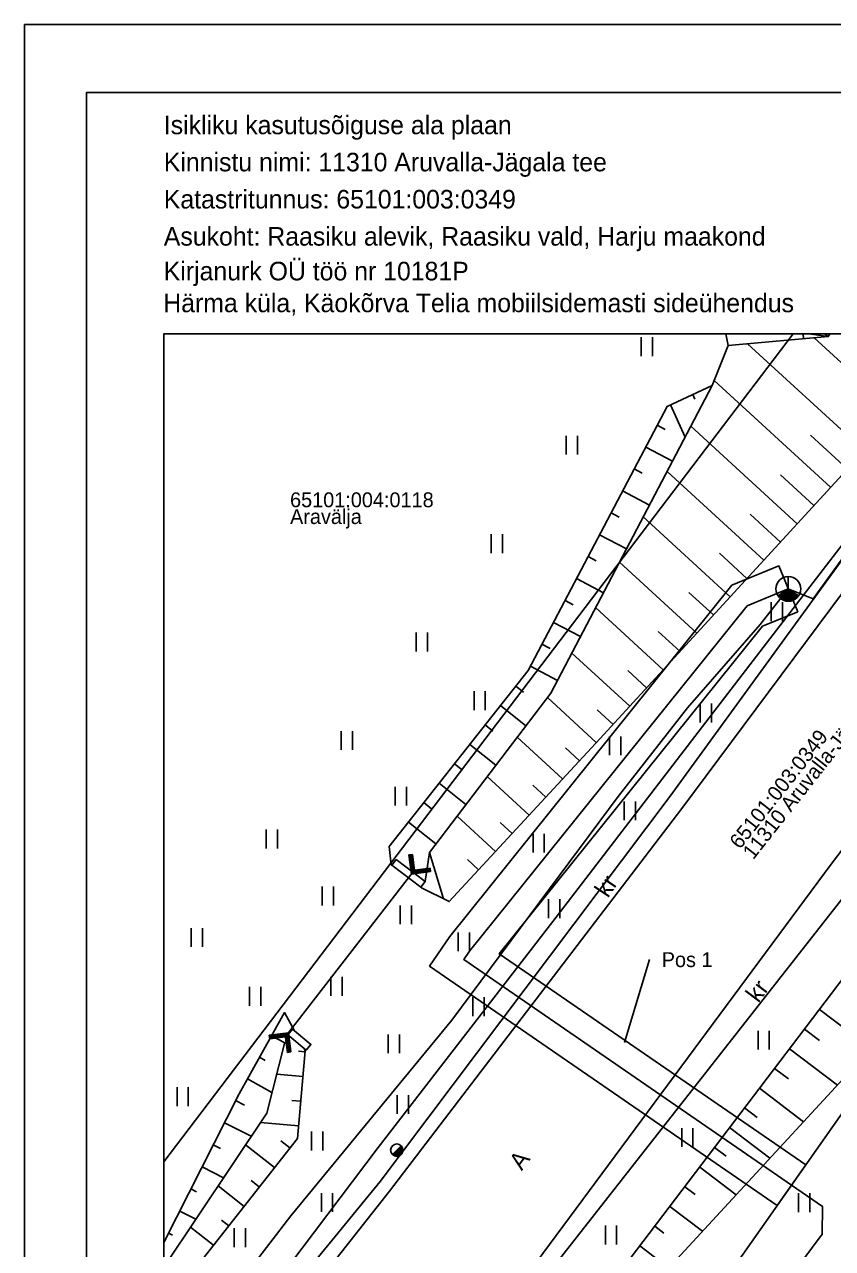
# Model space of a CAD drawing. Extents: x 565784.5 to 565837, y 6571808.3 to 6571882.6.
# Drawn here: x 565784.51 to 565817.14, y 6571833.15 to 6571882.59 of the extents above; entities that cross this region are included whole.
import ezdxf

# ---------------------------------------------------------------- set-up
doc = ezdxf.new("R2010")
doc.units = 0
for name, color, linetype in [('HALJASTUS', 7, 'Continuous'), ('KASUTUSALA', 7, 'Continuous'), ('PIIR', 7, 'Continuous'), ('POST', 7, 'Continuous'), ('PR_SIDE', 7, 'Continuous'), ('RELJEEF', 7, 'Continuous'), ('SIKAEV', 7, 'Continuous'), ('SITRASS', 7, 'Continuous'), ('TEE', 7, 'Continuous'), ('TRUUP', 7, 'Continuous'), ('VORMISTUS', 7, 'Continuous')]:
    doc.layers.add(name, color=color, linetype=linetype)

msp = doc.modelspace()

# ---------------------------------------------------------------- linework, layer by layer
at = {"layer": 'HALJASTUS'}
for p, q in [((565809.42, 6571869.956), (565809.42, 6571869.195)), ((565809.875, 6571869.956), (565809.875, 6571869.195)), ((565806.389, 6571865.979), (565806.389, 6571865.218)), ((565806.844, 6571865.979), (565806.844, 6571865.218)), ((565803.358, 6571862.003), (565803.358, 6571861.242)), ((565803.813, 6571862.003), (565803.813, 6571861.242)), ((565814.662, 6571859.257), (565814.662, 6571858.496)), ((565815.117, 6571859.257), (565815.117, 6571858.496)), ((565800.327, 6571858.026), (565800.327, 6571857.265)), ((565800.783, 6571858.026), (565800.783, 6571857.265)), ((565802.664, 6571855.656), (565802.664, 6571854.895)), ((565803.119, 6571855.656), (565803.119, 6571854.895)), ((565811.794, 6571855.164), (565811.794, 6571854.403)), ((565812.249, 6571855.164), (565812.249, 6571854.403)), ((565797.297, 6571854.049), (565797.297, 6571853.288)), ((565797.752, 6571854.049), (565797.752, 6571853.288)), ((565808.132, 6571853.836), (565808.132, 6571853.075)), ((565808.587, 6571853.836), (565808.587, 6571853.075)), ((565799.48, 6571851.8), (565799.48, 6571851.039)), ((565799.935, 6571851.8), (565799.935, 6571851.039)), ((565808.734, 6571851.209), (565808.734, 6571850.448)), ((565809.189, 6571851.209), (565809.189, 6571850.448)), ((565794.266, 6571850.073), (565794.266, 6571849.312)), ((565794.721, 6571850.073), (565794.721, 6571849.312)), ((565805.047, 6571849.901), (565805.047, 6571849.14)), ((565805.502, 6571849.901), (565805.502, 6571849.14)), ((565796.526, 6571847.768), (565796.526, 6571847.007)), ((565796.981, 6571847.768), (565796.981, 6571847.007)), ((565805.675, 6571847.254), (565805.675, 6571846.493)), ((565806.13, 6571847.254), (565806.13, 6571846.493)), ((565799.682, 6571847.009), (565799.682, 6571846.248)), ((565800.137, 6571847.009), (565800.137, 6571846.248)), ((565791.235, 6571846.096), (565791.235, 6571845.335)), ((565791.69, 6571846.096), (565791.69, 6571845.335)), ((565802.029, 6571845.917), (565802.029, 6571845.156)), ((565802.484, 6571845.917), (565802.484, 6571845.156)), ((565796.879, 6571844.119), (565796.879, 6571843.357)), ((565797.334, 6571844.119), (565797.334, 6571843.357)), ((565793.597, 6571843.716), (565793.597, 6571842.955)), ((565794.052, 6571843.716), (565794.052, 6571842.955)), ((565802.616, 6571843.299), (565802.616, 6571842.538)), ((565803.071, 6571843.299), (565803.071, 6571842.538)), ((565799.2, 6571841.795), (565799.2, 6571841.034)), ((565799.655, 6571841.795), (565799.655, 6571841.034)), ((565814.134, 6571841.947), (565814.134, 6571841.186)), ((565814.589, 6571841.947), (565814.589, 6571841.186)), ((565790.667, 6571839.664), (565790.667, 6571838.903)), ((565791.122, 6571839.664), (565791.122, 6571838.903)), ((565799.557, 6571839.345), (565799.557, 6571838.583)), ((565800.012, 6571839.345), (565800.012, 6571838.583)), ((565796.096, 6571837.876), (565796.096, 6571837.115)), ((565796.551, 6571837.876), (565796.551, 6571837.115)), ((565811.05, 6571838.011), (565811.05, 6571837.25)), ((565811.506, 6571838.011), (565811.506, 6571837.25)), ((565796.498, 6571835.39), (565796.498, 6571834.628)), ((565796.953, 6571835.39), (565796.953, 6571834.628)), ((565815.772, 6571835.381), (565815.772, 6571834.619)), ((565816.228, 6571835.381), (565816.228, 6571834.619)), ((565792.978, 6571833.966), (565792.978, 6571833.205)), ((565793.433, 6571833.966), (565793.433, 6571833.205)), ((565807.967, 6571834.076), (565807.967, 6571833.314)), ((565808.422, 6571834.076), (565808.422, 6571833.314))]:
    msp.add_line(p, q, dxfattribs=at)
at = {"layer": 'KASUTUSALA'}
msp.add_lwpolyline([(565815.738, 6571858.869), (565814.976, 6571860.719), (565813.082, 6571859.939), (565801.68, 6571845.752), (565800.866, 6571844.561), (565814.913, 6571834.887), (565816.063, 6571836.523), (565803.681, 6571845.05), (565814.319, 6571858.285)], close=True, dxfattribs=at)
at = {"layer": 'PIIR'}
for points in [[(565790.132, 6571836.654), (565815.559, 6571870.093)], [(565815.559, 6571870.093), (565790.132, 6571836.654)], [(565831.382, 6571858.328), (565803.59, 6571818.77), (565802.507, 6571817.593)], [(565803.77, 6571817.593), (565803.59, 6571818.77), (565831.382, 6571858.328)]]:
    msp.add_lwpolyline(points, dxfattribs=at)
at = {"layer": 'POST'}
msp.add_line((565799.366, 6571836.946), (565799.719, 6571837.299), dxfattribs=at)
msp.add_circle((565799.543, 6571837.122), 0.25, dxfattribs=at)
for radius, start, end in [(0.225, 224.8541, 45.0356), (0.2, 224.8427, 45.047), (0.175, 224.8281, 45.0616), (0.15, 224.8087, 45.081), (0.125, 224.7814, 45.1083), (0.1, 224.7406, 45.1491), (0.075, 224.6725, 45.2172), (0.05, 224.5363, 45.3534), (0.025, 224.1278, 45.7619)]:
    msp.add_arc((565799.543, 6571837.122), radius, start, end, dxfattribs=at)
at = {"layer": 'PR_SIDE'}
msp.add_lwpolyline([(565805.611, 6571817.593), (565805.669, 6571817.785), (565806.328, 6571819.758), (565816.728, 6571833.724), (565816.733, 6571834.847), (565802.253, 6571844.819), (565802.484, 6571845.156), (565813.7, 6571859.112), (565815.357, 6571859.794)], dxfattribs=at)
at = {"layer": 'RELJEEF'}
for p, q in [((565815.972, 6571869.899), (565815.955, 6571870.093)), ((565819.772, 6571866.846), (565816.402, 6571869.937)), ((565818.419, 6571865.372), (565813.704, 6571869.699)), ((565817.067, 6571863.898), (565812.369, 6571868.209)), ((565811.501, 6571867.642), (565811.584, 6571867.46)), ((565810.593, 6571867.224), (565811.193, 6571865.92)), ((565810.062, 6571866.407), (565810.388, 6571866.236)), ((565815.715, 6571862.425), (565811.424, 6571866.361)), ((565817.743, 6571864.635), (565816.249, 6571866.006)), ((565809.597, 6571865.522), (565810.683, 6571864.95)), ((565809.131, 6571864.637), (565809.457, 6571864.465)), ((565814.363, 6571860.951), (565810.462, 6571864.53)), ((565816.391, 6571863.162), (565815.046, 6571864.396)), ((565808.666, 6571863.752), (565809.753, 6571863.18)), ((565808.2, 6571862.867), (565808.527, 6571862.695)), ((565813.011, 6571859.477), (565809.5, 6571862.699)), ((565815.039, 6571861.688), (565813.81, 6571862.815)), ((565807.735, 6571861.982), (565808.823, 6571861.409)), ((565807.269, 6571861.097), (565807.596, 6571860.925)), ((565813.687, 6571860.214), (565812.575, 6571861.234)), ((565811.659, 6571858.003), (565808.538, 6571860.867)), ((565806.804, 6571860.212), (565807.892, 6571859.639)), ((565812.335, 6571858.74), (565811.34, 6571859.653)), ((565806.338, 6571859.327), (565806.665, 6571859.155)), ((565810.307, 6571856.53), (565807.576, 6571859.036)), ((565805.873, 6571858.442), (565806.962, 6571857.868)), ((565810.983, 6571857.267), (565810.105, 6571858.072)), ((565805.407, 6571857.557), (565805.734, 6571857.385)), ((565808.955, 6571855.056), (565806.613, 6571857.204)), ((565804.942, 6571856.671), (565806.032, 6571856.098)), ((565809.631, 6571855.793), (565808.87, 6571856.491)), ((565804.351, 6571855.868), (565804.656, 6571855.627)), ((565803.731, 6571855.083), (565804.761, 6571854.269)), ((565807.602, 6571853.583), (565805.629, 6571855.41)), ((565808.279, 6571854.319), (565807.635, 6571854.91)), ((565803.111, 6571854.298), (565803.424, 6571854.051)), ((565802.491, 6571853.514), (565803.549, 6571852.678)), ((565806.243, 6571852.115), (565804.412, 6571853.811)), ((565806.923, 6571852.849), (565806.352, 6571853.378)), ((565801.871, 6571852.729), (565802.193, 6571852.475)), ((565804.885, 6571850.648), (565803.194, 6571852.213)), ((565801.251, 6571851.945), (565802.337, 6571851.087)), ((565805.564, 6571851.382), (565805.036, 6571851.871)), ((565800.631, 6571851.16), (565800.961, 6571850.9)), ((565803.526, 6571849.18), (565801.977, 6571850.614)), ((565800.011, 6571850.376), (565801.125, 6571849.495)), ((565804.205, 6571849.914), (565803.719, 6571850.364)), ((565800.688, 6571847.978), (565800.861, 6571849.149)), ((565801.433, 6571847.277), (565800.861, 6571849.149)), ((565802.847, 6571848.446), (565802.403, 6571848.857)), ((565816.618, 6571842.808), (565818.701, 6571841.225)), ((565794.49, 6571841.746), (565795.017, 6571841.451)), ((565816.013, 6571842.012), (565816.615, 6571841.555)), ((565815.408, 6571841.216), (565817.338, 6571839.749)), ((565794.001, 6571840.873), (565794.229, 6571840.746)), ((565795.843, 6571841.093), (565795.574, 6571841.117)), ((565795.754, 6571840.097), (565794.694, 6571840.192)), ((565814.803, 6571840.42), (565815.359, 6571839.997)), ((565793.513, 6571840.001), (565794.503, 6571839.447)), ((565814.198, 6571839.624), (565815.975, 6571838.272)), ((565793.036, 6571839.122), (565793.393, 6571838.941)), ((565795.664, 6571839.101), (565795.298, 6571839.134)), ((565813.592, 6571838.828), (565814.103, 6571838.44)), ((565792.585, 6571838.23), (565793.665, 6571837.683)), ((565795.575, 6571838.105), (565794.04, 6571838.243)), ((565812.987, 6571838.032), (565814.612, 6571836.796)), ((565792.133, 6571837.338), (565792.424, 6571837.19)), ((565794.609, 6571836.425), (565793.438, 6571837.344)), ((565795.226, 6571837.212), (565794.857, 6571837.502)), ((565812.382, 6571837.235), (565812.847, 6571836.882)), ((565791.681, 6571836.446), (565792.545, 6571836.008)), ((565811.777, 6571836.439), (565813.249, 6571835.32)), ((565793.991, 6571835.639), (565793.658, 6571835.9)), ((565791.229, 6571835.554), (565791.455, 6571835.439)), ((565793.374, 6571834.852), (565792.323, 6571835.677)), ((565811.172, 6571835.643), (565811.591, 6571835.325)), ((565810.567, 6571834.847), (565811.887, 6571833.844)), ((565790.777, 6571834.662), (565791.425, 6571834.333)), ((565792.757, 6571834.065), (565792.459, 6571834.298)), ((565790.325, 6571833.77), (565790.487, 6571833.688)), ((565792.139, 6571833.278), (565791.208, 6571834.009)), ((565809.961, 6571834.051), (565810.335, 6571833.767)), ((565809.356, 6571833.255), (565810.524, 6571832.368))]:
    msp.add_line(p, q, dxfattribs=at)
for points in [[(565800.51, 6571847.744), (565800.538, 6571847.723), (565801.66, 6571847.165), (565807.743, 6571853.735), (565820.396, 6571867.526), (565822.365, 6571870.093)], [(565816.969, 6571869.988), (565812.929, 6571869.63), (565812.828, 6571870.093)], [(565800.861, 6571849.149), (565805.762, 6571855.585), (565812.288, 6571868.004), (565812.929, 6571869.63)], [(565799.345, 6571848.635), (565799.323, 6571848.653), (565799.23, 6571849.388), (565804.852, 6571856.501), (565810.46, 6571867.163), (565812.288, 6571868.004)], [(565831.382, 6571861.091), (565830.033, 6571859.153), (565819.486, 6571846.581), (565806.328, 6571829.271), (565803.644, 6571823.76)], [(565830.061, 6571854.393), (565821.897, 6571844.686), (565807.174, 6571828.74), (565803.644, 6571823.76)], [(565790.132, 6571833.389), (565793.178, 6571839.402), (565795.011, 6571842.678), (565795.409, 6571841.942)], [(565790.132, 6571832.4), (565794.289, 6571838.617), (565795.026, 6571841.487)], [(565790.132, 6571830.72), (565795.529, 6571837.598), (565795.847, 6571841.134), (565795.788, 6571841.243)]]:
    msp.add_lwpolyline(points, dxfattribs=at)
at = {"layer": 'SIKAEV'}
for p, q in [((565815.357, 6571860.294), (565815.357, 6571859.794)), ((565815.357, 6571859.794), (565814.942, 6571859.519)), ((565815.357, 6571859.794), (565815.772, 6571859.519))]:
    msp.add_line(p, q, dxfattribs=at)
msp.add_circle((565815.357, 6571859.794), 0.5, dxfattribs=at)
for radius in [0.475, 0.45, 0.425, 0.4, 0.375, 0.35, 0.325, 0.3, 0.275, 0.25, 0.225, 0.2, 0.175, 0.15, 0.125, 0.1, 0.075, 0.05]:
    msp.add_arc((565815.357, 6571859.794), radius, 213.5305, 326.4695, dxfattribs=at)
at = {"layer": 'SITRASS'}
for points in [[(565790.132, 6571827.785), (565795.262, 6571834.475), (565801.765, 6571842.375), (565808.482, 6571851.414), (565811.284, 6571854.993), (565814.22, 6571858.353), (565815.357, 6571859.794), (565816.36, 6571859.39), (565822.04, 6571867.24), (565823.485, 6571869.196), (565824.132, 6571870.093)], [(565823.913, 6571870.093), (565819.589, 6571864.258), (565813.931, 6571856.898), (565805.842, 6571846.363), (565798.797, 6571837.231), (565791.619, 6571827.726), (565790.132, 6571825.916)]]:
    msp.add_lwpolyline(points, dxfattribs=at)
at = {"layer": 'TEE'}
for points in [[(565790.132, 6571825.178), (565798.874, 6571835.854), (565810.584, 6571851.423), (565821.499, 6571866.441), (565824.25, 6571870.093)], [(565790.132, 6571823.893), (565799.254, 6571835.472), (565811.058, 6571850.919), (565822.074, 6571865.705), (565825.255, 6571869.896)], [(565831.382, 6571863.074), (565828.407, 6571862.073), (565825.907, 6571860.285), (565817.092, 6571848.675), (565804.137, 6571831.188), (565797.898, 6571823.166), (565798.048, 6571821.994), (565800.139, 6571818.615), (565800.327, 6571817.593)], [(565831.382, 6571862.872), (565828.71, 6571861.712), (565827.373, 6571860.217), (565817.957, 6571847.828), (565804.535, 6571830.717), (565801.583, 6571826.805), (565800.955, 6571825.15), (565801.025, 6571821.866), (565801.467, 6571818.976), (565801.839, 6571817.593)]]:
    msp.add_lwpolyline(points, dxfattribs=at)
at = {"layer": 'TRUUP'}
for p, q in [((565800.176, 6571849.066), (565800.035, 6571849.048)), ((565800.035, 6571849.048), (565800.133, 6571848.276)), ((565800.064, 6571849.051), (565800.042, 6571848.99)), ((565800.092, 6571849.055), (565800.049, 6571848.935)), ((565800.12, 6571849.058), (565800.056, 6571848.88)), ((565800.148, 6571849.062), (565800.063, 6571848.825)), ((565800.175, 6571849.066), (565800.071, 6571848.769)), ((565800.106, 6571849.057), (565800.195, 6571848.355)), ((565800.176, 6571849.066), (565800.257, 6571848.435)), ((565800.183, 6571849.013), (565800.078, 6571848.714)), ((565800.19, 6571848.957), (565800.085, 6571848.659)), ((565800.197, 6571848.902), (565800.092, 6571848.604)), ((565800.204, 6571848.847), (565800.099, 6571848.549)), ((565800.211, 6571848.792), (565800.106, 6571848.494)), ((565800.218, 6571848.737), (565800.113, 6571848.439)), ((565800.225, 6571848.682), (565800.12, 6571848.384)), ((565800.232, 6571848.627), (565800.127, 6571848.329)), ((565800.239, 6571848.572), (565800.135, 6571848.276)), ((565795.106, 6571841.78), (565800.195, 6571848.355)), ((565800.133, 6571848.276), (565800.905, 6571848.374)), ((565800.246, 6571848.517), (565800.162, 6571848.279)), ((565800.253, 6571848.461), (565800.19, 6571848.283)), ((565800.195, 6571848.355), (565800.896, 6571848.445)), ((565800.271, 6571848.437), (565800.218, 6571848.286)), ((565800.299, 6571848.44), (565800.246, 6571848.29)), ((565800.257, 6571848.435), (565800.887, 6571848.515)), ((565800.327, 6571848.444), (565800.273, 6571848.293)), ((565800.354, 6571848.447), (565800.301, 6571848.297)), ((565800.382, 6571848.451), (565800.329, 6571848.301)), ((565800.41, 6571848.454), (565800.357, 6571848.304)), ((565800.438, 6571848.458), (565800.384, 6571848.308)), ((565800.465, 6571848.461), (565800.412, 6571848.311)), ((565800.493, 6571848.465), (565800.44, 6571848.315)), ((565800.521, 6571848.469), (565800.468, 6571848.318)), ((565800.549, 6571848.472), (565800.496, 6571848.322)), ((565800.576, 6571848.476), (565800.523, 6571848.325)), ((565800.604, 6571848.479), (565800.551, 6571848.329)), ((565800.632, 6571848.483), (565800.579, 6571848.332)), ((565800.66, 6571848.486), (565800.607, 6571848.336)), ((565800.688, 6571848.49), (565800.634, 6571848.339)), ((565800.715, 6571848.493), (565800.662, 6571848.343)), ((565800.743, 6571848.497), (565800.69, 6571848.347)), ((565800.771, 6571848.5), (565800.718, 6571848.35)), ((565800.799, 6571848.504), (565800.745, 6571848.354)), ((565800.826, 6571848.507), (565800.773, 6571848.357)), ((565800.854, 6571848.511), (565800.801, 6571848.361)), ((565800.882, 6571848.514), (565800.829, 6571848.364)), ((565800.893, 6571848.471), (565800.857, 6571848.368)), ((565800.9, 6571848.416), (565800.884, 6571848.371)), ((565800.887, 6571848.515), (565800.905, 6571848.374)), ((565795.167, 6571841.86), (565794.395, 6571841.762)), ((565794.413, 6571841.62), (565794.395, 6571841.762)), ((565794.401, 6571841.72), (565794.416, 6571841.764)), ((565795.106, 6571841.78), (565794.404, 6571841.691)), ((565794.408, 6571841.665), (565794.444, 6571841.768)), ((565795.044, 6571841.701), (565794.413, 6571841.62)), ((565794.419, 6571841.621), (565794.472, 6571841.771)), ((565794.446, 6571841.625), (565794.5, 6571841.775)), ((565794.474, 6571841.628), (565794.527, 6571841.779)), ((565794.502, 6571841.632), (565794.555, 6571841.782)), ((565794.53, 6571841.635), (565794.583, 6571841.786)), ((565794.558, 6571841.639), (565794.611, 6571841.789)), ((565794.585, 6571841.642), (565794.638, 6571841.793)), ((565794.613, 6571841.646), (565794.666, 6571841.796)), ((565794.641, 6571841.649), (565794.694, 6571841.8)), ((565794.669, 6571841.653), (565794.722, 6571841.803)), ((565794.696, 6571841.657), (565794.75, 6571841.807)), ((565794.724, 6571841.66), (565794.777, 6571841.81)), ((565794.752, 6571841.664), (565794.805, 6571841.814)), ((565794.78, 6571841.667), (565794.833, 6571841.817)), ((565794.807, 6571841.671), (565794.861, 6571841.821)), ((565794.835, 6571841.674), (565794.888, 6571841.824)), ((565794.863, 6571841.678), (565794.916, 6571841.828)), ((565794.891, 6571841.681), (565794.944, 6571841.832)), ((565794.919, 6571841.685), (565794.972, 6571841.835)), ((565794.946, 6571841.688), (565794.999, 6571841.839)), ((565794.974, 6571841.692), (565795.027, 6571841.842)), ((565795.002, 6571841.695), (565795.055, 6571841.846)), ((565795.03, 6571841.699), (565795.083, 6571841.849)), ((565795.124, 6571841.07), (565795.044, 6571841.701)), ((565795.047, 6571841.674), (565795.111, 6571841.853)), ((565795.054, 6571841.619), (565795.138, 6571841.856)), ((565795.061, 6571841.564), (565795.166, 6571841.86)), ((565795.068, 6571841.509), (565795.174, 6571841.807)), ((565795.075, 6571841.454), (565795.181, 6571841.752)), ((565795.082, 6571841.399), (565795.188, 6571841.697)), ((565795.089, 6571841.344), (565795.195, 6571841.642)), ((565795.195, 6571841.079), (565795.106, 6571841.78)), ((565795.266, 6571841.088), (565795.167, 6571841.86)), ((565795.096, 6571841.288), (565795.202, 6571841.587)), ((565795.104, 6571841.233), (565795.209, 6571841.532)), ((565795.111, 6571841.178), (565795.216, 6571841.476)), ((565795.118, 6571841.123), (565795.223, 6571841.421)), ((565795.125, 6571841.07), (565795.23, 6571841.366)), ((565795.153, 6571841.074), (565795.237, 6571841.311)), ((565795.181, 6571841.077), (565795.244, 6571841.256)), ((565795.209, 6571841.081), (565795.251, 6571841.201)), ((565795.236, 6571841.084), (565795.258, 6571841.146)), ((565795.124, 6571841.07), (565795.266, 6571841.088))]:
    msp.add_line(p, q, dxfattribs=at)
for points in [[(565816.969, 6571869.988), (565816.182, 6571870.093)], [(565816.827, 6571870.093), (565816.969, 6571869.988), (565817.047, 6571870.093)]]:
    msp.add_lwpolyline(points, dxfattribs=at)
for points in [[(565799.524, 6571848.869), (565800.688, 6571847.978), (565800.51, 6571847.744), (565799.345, 6571848.635)], [(565795.327, 6571842.011), (565796.074, 6571841.393), (565795.884, 6571841.163), (565795.137, 6571841.781)]]:
    msp.add_lwpolyline(points, close=True, dxfattribs=at)
at = {"layer": 'VORMISTUS'}
msp.add_line((565808.737, 6571841.472), (565809.744, 6571844.818), dxfattribs=at)
for points in [[(565784.507, 6571882.593), (565837.007, 6571882.593), (565837.007, 6571808.343), (565784.507, 6571808.343)], [(565787.007, 6571811.093), (565834.507, 6571811.093), (565834.507, 6571879.843), (565787.007, 6571879.843)], [(565787.007, 6571879.843), (565834.507, 6571879.843), (565834.507, 6571811.093), (565787.007, 6571811.093)], [(565831.382, 6571817.593), (565790.132, 6571817.593), (565790.132, 6571870.093), (565831.382, 6571870.093)]]:
    msp.add_lwpolyline(points, close=True, dxfattribs=at)

# ---------------------------------------------------------------- texts
at = {"layer": 'PIIR'}
for s, p in [('65101:004:0118', (565795.233, 6571863.093)), ('Aravälja', (565795.233, 6571862.413))]:
    msp.add_text(s, height=0.6, dxfattribs=at).set_placement(p)
for s, p in [('11310 Aruvalla-Jägala tee', (565813.94, 6571848.826)), ('65101:003:0349', (565813.405, 6571849.248))]:
    msp.add_text(s, height=0.6, rotation=51.7649, dxfattribs=at).set_placement(p)
at = {"layer": 'TEE'}
for s, rotation, p in [('kr', 56.1256, (565808.069, 6571847.279)), ('kr', 52.9828, (565814.143, 6571843.041)), ('A', 53.7346, (565804.591, 6571836.267))]:
    msp.add_text(s, height=0.7, rotation=rotation, dxfattribs=at).set_placement(p)
at = {"layer": 'VORMISTUS'}
for s, p in [('Isikliku kasutusõiguse ala plaan', (565790.134, 6571878.16)), ('Kirjanurk OÜ töö nr 10181P', (565790.131, 6571872.257)), ('Härma küla, Käokõrva Telia mobiilsidemasti sideühendus', (565790.111, 6571870.971))]:
    msp.add_text(s, height=0.75, rotation=360, dxfattribs=at).set_placement(p)
for s, height, p in [('Kinnistu nimi: 11310 Aruvalla-Jägala tee', 0.75, (565790.134, 6571876.66)), ('Katastritunnus: 65101:003:0349', 0.75, (565790.134, 6571875.16)), ('Asukoht: Raasiku alevik, Raasiku vald, Harju maakond', 0.75, (565790.134, 6571873.66)), ('Pos 1', 0.6, (565810.244, 6571844.518))]:
    msp.add_text(s, height=height, dxfattribs=at).set_placement(p)

doc.saveas('drawing.dxf')
